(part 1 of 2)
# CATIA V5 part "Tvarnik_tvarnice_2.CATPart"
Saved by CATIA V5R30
Part number: Tvarnik_tvarnice_1
Bounding box of the stored display mesh (mm): x -44.4 to 47.6, y -90 to 90, z -90 to 90
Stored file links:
  E:\Bakalarka\Model\Forma_v7\Tvarnik_tvarnice_2.CATPart
  E:\Bakalarka\Model\Sestava_formy_1\Vicko.CATPart
  E:\Bakalarka\Model\Sestava_formy\Tvarnik_tvarnice.CATPart
  E:\Bakalarka\Model\Forma_v7\Sestava_tvarniku_tvarnice.CATProduct
  E:\Bakalarka\Model\Sestava_formy_1\Forma_Sestava_tvarniku_tvarnice.CATPart
  E:\Bakalarka\Model\Chyba catie 2\Forma_Sestava_tvarniku_tvarnice.CATPart
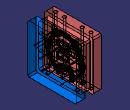
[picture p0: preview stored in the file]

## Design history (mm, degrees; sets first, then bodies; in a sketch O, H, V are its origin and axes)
Body1 (main body)
  Solid1: solid without history
  Body2 "Result of __DrillHole"
    Solid2: linked copy from another document
  Assemble1 "DrillHoleEjector_E1710_7.1": tool Body2
  Body3 "Result of __DrillHole"
    Solid3: linked copy from another document
  Assemble2 "DrillHoleEjector_E1710_8.1": tool Body3
  Body4 "Result of __DrillHole"
    Solid4: linked copy from another document
  Assemble3 "DrillHoleEjector_E1710_9.1": tool Body4
  Body5 "Result of __DrillHole"
    Solid5: linked copy from another document
  Assemble4 "DrillHoleEjector_E1710_10.1": tool Body5
  Body6 "Result of __DrillHole"
    Solid6: linked copy from another document
  Assemble5 "DrillHoleEjector_E1710_11.1": tool Body6
  Body7 "Result of __DrillHole"
    Solid7: linked copy from another document
  Assemble6 "DrillHoleEjector_E1710_17.1": tool Body7
  Body8 "Result of __DrillHole"
    Solid8: linked copy from another document
  Assemble7 "DrillHoleEjector_E1710_18.1": tool Body8
  Body9 "Result of __DrillHole"
    Solid9: linked copy from another document
  Assemble8 "DrillHoleEjector_E1710_19.1": tool Body9
  Body10 "Result of __DrillHole"
    Solid10: linked copy from another document
  Assemble9 "DrillHoleEjector_E1710_20.1": tool Body10
  Body11 "Result of __DrillHole"
    Solid11: linked copy from another document
  Assemble10 "DrillHoleEjector_E1710_21.1": tool Body11
  Body12 "Result of __DrillHole"
    Solid12: linked copy from another document
  Assemble11 "DrillHoleEjector_E1710_31.1": tool Body12
  Body13 "Result of __DrillHole"
    Solid13: linked copy from another document
  Assemble12 "DrillHoleEjector_E1710_32.1": tool Body13
  Body14 "Result of __DrillHole"
    Solid14: linked copy from another document
  Assemble13 "DrillHoleEjector_E1710_33.1": tool Body14
  Body15 "Result of __DrillHole"
    Solid15: linked copy from another document
  Assemble14 "DrillHoleEjector_E1710_34.1": tool Body15
  Body16 "Result of __DrillHole"
    Solid16: linked copy from another document
  Assemble15 "DrillHoleEjector_E1710_35.1": tool Body16
  Body17 "Result of __DrillHole"
    Solid17: linked copy from another document
  Assemble16 "DrillHoleEjector_E1710_36.1": tool Body17
  Body18 "Result of __DrillHole"
    Solid18: linked copy from another document
  Assemble17 "DrillHoleEjector_E1710_37.1": tool Body18
  Body19 "Result of __DrillHole"
    Solid19: linked copy from another document
  Assemble18 "DrillHoleEjector_E1710_1.2": tool Body19
  Body20 "Result of __DrillHole"
    Solid20: linked copy from another document
  Assemble19 "DrillHoleEjector_E1710_2.2": tool Body20
  Body21 "Result of __DrillHole"
    Solid21: linked copy from another document
  Assemble20 "DrillHoleEjector_E1710_3.2": tool Body21
  Body22 "Result of __DrillHole"
    Solid22: linked copy from another document
  Assemble21 "DrillHoleEjector_E1710_4.2": tool Body22
Body23 "Tvarnik"
  Sketch1 on face of Solid23, origin (1.6, 0, 0), H (0, 1, 0), V (0, 0, 1)
    line L1 (80, 80) -> (80, -80)
    line L2 (80, -80) -> (-80, -80)
    line L3 (-80, -80) -> (-80, 80)
    line L4 (-80, 80) -> (80, 80)
    length L4 = 160
    length L1 = 160
    vertical: L1 V, L3 V
    horizontal: L2 H, L4 H
    equidistance: L1 L3 O, L2 L4 O
  Pad1: profile Sketch1, direction (-1, 0, 0), length 16
  Body24 "Vicko"
    Solid23: linked copy from another document
  Remove1: tool Body24
  Sketch2 on start face of Pad1, origin (1.6, 0, 0), H (0, 1, 0), V (0, 0, 1)
    projected arc E1 centre (0, 0) radius 71.425 from (33.2826, 63.1965) to (-30.4134, 64.6263) ccw from edge [face of Solid23 | face of Solid23]
    projected arc E2 centre (-31.265, 66.4359) radius 2 from (-30.8799, 64.4733) to (-30.4134, 64.6263) ccw from edge [face of Solid23 | face of Solid23]
    projected arc E3 centre (-31.265, 66.4359) radius 2 from (-32.3394, 64.749) to (-30.8799, 64.4733) ccw from edge [face of Solid23 | face of Solid23]
    projected arc E4 centre (-35.5625, 59.6882) radius 6 from (-32.3394, 64.749) to (-41.5474, 59.2628) ccw from edge [face of Solid23 | face of Solid23]
    projected arc E5 centre (-43.5423, 59.121) radius 2 from (-42.3563, 57.5107) to (-41.5474, 59.2628) ccw from edge [face of Solid23 | face of Solid23]
    projected arc E6 centre (0, 0) radius 71.425 from (-42.3563, 57.5107) to (-68.5299, 20.1291) ccw from edge [face of Solid23 | face of Solid23]
    projected arc E7 centre (-70.4489, 20.6927) radius 2 from (-69.8997, 18.7696) to (-68.5299, 20.1291) ccw from edge [face of Solid23 | face of Solid23]
    projected arc E8 centre (-68.2522, 13.0002) radius 6 from (-69.8997, 18.7696) to (-71.9052, 8.2404) ccw from edge [face of Solid23 | face of Solid23]
    projected arc E9 centre (-73.1229, 6.6538) radius 2 from (-71.1311, 6.4726) to (-71.9052, 8.2404) ccw from edge [face of Solid23 | face of Solid23]
    projected arc E10 centre (0, 0) radius 71.425 from (-71.1311, 6.4726) to (-64.1739, -31.3568) ccw from edge [face of Solid23 | face of Solid23]
    projected arc E11 centre (0, 0) radius 71.425 from (-64.1739, -31.3568) to (-44.634, -55.7614) ccw from edge [face of Solid23 | face of Solid23]
    projected arc E12 centre (-44.9464, -56.1518) radius 0.5 from (-44.5334, -55.87) to (-44.634, -55.7614) ccw from edge [face of Solid23 | face of Solid23]
    projected line E13 (-44.5334, -55.87) -> (-43.5459, -57.3175) from edge [face of Solid23 | face of Solid23]
    projected arc E14 centre (-43.1328, -57.0357) radius 0.5 from (-43.5459, -57.3175) to (-42.9183, -57.4874) ccw from edge [face of Solid23 | face of Solid23]
    projected line E15 (-42.9183, -57.4874) -> (-42.6019, -57.337) from edge [face of Solid23 | face of Solid23]
    projected arc E16 centre (-42.6448, -57.2467) radius 0.1 from (-42.6019, -57.337) to (-42.5892, -57.3299) ccw from edge [face of Solid23 | face of Solid23]
    projected arc E17 centre (-38.7, -63.15) radius 7 from (-37.0577, -56.3454) to (-42.5892, -57.3299) ccw from edge [face of Solid23 | face of Solid23]
    projected arc E19 centre (-39.7026, -63.67) radius 8 from (-33.5229, -68.7505) to (-31.75, -64.54) ccw from edge [face of Solid23 | face of Solid23]
    projected arc E20 centre (-33.4456, -68.814) radius 0.1 from (-33.5229, -68.7505) to (-33.494, -68.9015) ccw from edge [face of Solid23 | face of Solid23]
    projected line E21 (-33.494, -68.9015) -> (-28.2581, -71.7985) from edge [face of Solid23 | face of Solid23]
    projected line E22 (-25.7474, -73.1876) -> (-28.2581, -71.7985) from edge [face of Solid23 | face of Solid23]
    projected arc E23 centre (-25.7, -67.2) radius 6 from (-25.7, -73.2) to (-19.7, -67.2) ccw from edge [face of Solid23 | face of Solid23]
    projected line E24 (-19.7, -52.2166) -> (-19.7, -67.2) from edge [face of Solid23 | face of Solid23]
    projected arc E25 centre (-12.6167, -52.2166) radius 7.0833 from (-14.8563, -45.4967) to (-19.7, -52.2166) ccw from edge [face of Solid23 | face of Solid23]
    projected arc E26 centre (-12.6167, -52.2166) radius 7.0833 from (-13.7, -45.2166) to (-14.8563, -45.4967) ccw from edge [face of Solid23 | face of Solid23]
    projected arc E27 centre (-1.5593, -117.2) radius 73 from (8.5876, -44.9086) to (-13.7, -45.2166) ccw from edge [face of Solid23 | face of Solid23]
    projected arc E28 centre (-1.5593, -117.2) radius 73 from (12.028, -45.4756) to (8.5876, -44.9086) ccw from edge [face of Solid23 | face of Solid23]
    projected arc E29 centre (10.55, -54.5084) radius 9.15 from (14.5407, -46.2746) to (12.2, -45.5084) ccw from edge [face of Solid23 | face of Solid23]
    projected arc E30 centre (-1.5593, -117.2) radius 73 from (12.2, -45.5084) to (12.028, -45.4756) ccw from edge [face of Solid23 | face of Solid23]
    projected arc E31 centre (10.55, -54.5084) radius 9.15 from (19.7, -54.5084) to (14.5407, -46.2746) ccw from edge [face of Solid23 | face of Solid23]
    projected line E32 (19.7, -54.5084) -> (19.7, -65.95) from edge [face of Solid23 | face of Solid23]
    projected arc E33 centre (26.95, -65.95) radius 7.25 from (19.7, -65.95) to (26.95, -73.2) ccw from edge [face of Solid23 | face of Solid23]
    projected line E34 (26.95, -73.2) -> (27.1807, -73.2) from edge [face of Solid23 | face of Solid23]
    projected line E35 (27.2179, -73.1928) -> (29.0487, -72.4522) from edge [face of Solid23 | face of Solid23]
    projected line E36 (27.2179, -73.1928) -> (27.1999, -73.1995) from edge [face of Solid23 | face of Solid23]
    projected line E37 (27.1999, -73.1995) -> (27.1807, -73.2) from edge [face of Solid23 | face of Solid23]
    projected arc E38 centre (27.2, -65.7) radius 7 from (29.0596, -72.4485) to (34.2, -65.7) ccw from edge [face of Solid23 | face of Solid23]
    projected line E39 (29.054, -72.45) -> (29.0596, -72.4485) from edge [face of Solid23 | face of Solid23]
    projected line E40 (29.0487, -72.4522) -> (29.054, -72.45) from edge [face of Solid23 | face of Solid23]
    projected arc E41 centre (39.6, -65.7) radius 5.4 from (34.6823, -63.4692) to (34.2, -65.7) ccw from edge [face of Solid23 | face of Solid23]
    projected line E42 (34.6907, -63.4503) -> (34.6823, -63.4692) from edge [face of Solid23 | face of Solid23]
    projected arc E43 centre (34.5768, -63.4037) radius 0.123 from (34.6907, -63.4503) to (34.6998, -63.4087) ccw from edge [face of Solid23 | face of Solid23]
    projected line E44 (34.7, -63.3874) -> (34.6998, -63.4087) from edge [face of Solid23 | face of Solid23]
    projected line E45 (34.7, -63.3874) -> (34.7, -62.4295) from edge [face of Solid23 | face of Solid23]
    projected arc E46 centre (0, 0) radius 71.425 from (34.7, -62.4295) to (69.8826, -14.7632) ccw from edge [face of Solid23 | face of Solid23]
    projected arc E47 centre (70.861, -14.9699) radius 1 from (70.1987, -14.2207) to (69.8826, -14.7632) ccw from edge [face of Solid23 | face of Solid23]
    projected line E48 (70.1987, -14.2207) -> (71.6567, -12.9317) from edge [face of Solid23 | face of Solid23]
    projected line E49 (71.6567, -12.9317) -> (72.0071, -12.6219) from edge [face of Solid23 | face of Solid23]
    projected line E50 (72.1405, -12.504) -> (72.0071, -12.6219) from edge [face of Solid23 | face of Solid23]
    projected arc E51 centre (72.4717, -12.8786) radius 0.5 from (72.2645, -12.4235) to (72.1405, -12.504) ccw from edge [face of Solid23 | face of Solid23]
    projected arc E52 centre (69.7785, -6.9628) radius 6 from (72.2645, -12.4235) to (75.4588, -5.0305) ccw from edge [face of Solid23 | face of Solid23]
    projected line E53 (70.9819, 8.13) -> (75.4588, -5.0305) from edge [face of Solid23 | face of Solid23]
    projected arc E54 centre (69.5316, 12.3887) radius 4.4 from (65.7164, 14.5806) to (70.8571, 8.1931) ccw from edge [face of Solid23 | face of Solid23]
    projected line E55 (65.7164, 14.5806) -> (68.6344, 19.6597) from edge [face of Solid23 | face of Solid23]
    projected arc E56 centre (68.5476, 19.7096) radius 0.1001 from (68.6357, 19.662) to (68.6445, 19.7346) ccw from edge [face of Solid23 | face of Solid23]
    projected arc E57 centre (0, 0) radius 71.425 from (68.6438, 19.7372) to (44.8942, 55.5522) ccw from edge [face of Solid23 | face of Solid23]
    projected arc E58 centre (46.1513, 57.1077) radius 2 from (44.1679, 56.8506) to (44.8942, 55.5522) ccw from edge [face of Solid23 | face of Solid23]
    projected arc E59 centre (46.1513, 57.1077) radius 2 from (44.1647, 57.3389) to (44.1679, 56.8506) ccw from edge [face of Solid23 | face of Solid23]
    projected arc E60 centre (38.2049, 58.0324) radius 6 from (44.1647, 57.3389) to (35.2121, 63.2327) ccw from edge [face of Solid23 | face of Solid23]
    projected arc E61 centre (34.2145, 64.9661) radius 2 from (34.4133, 62.976) to (35.2121, 63.2327) ccw from edge [face of Solid23 | face of Solid23]
    projected arc E62 centre (34.2145, 64.9661) radius 2 from (33.2826, 63.1965) to (34.4133, 62.976) ccw from edge [face of Solid23 | face of Solid23]
    line L1 (68.6445, 19.7346) -> (68.6437, 19.7374)
    line L2 (-25.7, -73.2) -> (-25.7474, -73.1876)
    arc A1 centre (70.8987, 8.1188) radius 0.0834 from (70.9741, 8.1546) to (70.8713, 8.1976) ccw
    line L3 (70.8571, 8.1931) -> (70.8673, 8.1964)
    line L4 (70.9819, 8.13) -> (70.9741, 8.1546)
    point P129 (70.8713, 8.1976)
    line L5 (70.8673, 8.1964) -> (70.8713, 8.1976)
    point P130 (70.8713, 8.1976)
    line L6 (68.6344, 19.6597) -> (68.6357, 19.662)
    projected line E63 (-80, -80) -> (80, -80) from edge [face of Pad1 from Sketch1.L2 | start face of Pad1]
    projected line E64 (80, -80) -> (80, 80) from edge [face of Pad1 from Sketch1.L1 | start face of Pad1]
    projected line E65 (80, 80) -> (-80, 80) from edge [face of Pad1 from Sketch1.L4 | start face of Pad1]
    projected line E66 (-80, 80) -> (-80, -80) from edge [face of Pad1 from Sketch1.L3 | start face of Pad1]
    radius A1 = 0.0834
    distance P130 P129 = 0
    tangency: L1 E57, A1 E54, L3 E54
    perpendicularity: L4 L3
    coincidence: L3 P129, P130 E54
  Pocket1: profile Sketch2, direction (-1, 0, 0), length 16
  Sketch3 on end face of Pad1, origin (-14.4, 0, 0), H (0, -1, 0), V (0, 0, 1)
    line L1 (85.4438, 86.0089) -> (85.4438, -86.0089)
    line L2 (85.4438, -86.0089) -> (-85.4438, -86.0089)
    line L3 (-85.4438, -86.0089) -> (-85.4438, 86.0089)
    line L4 (-85.4438, 86.0089) -> (85.4438, 86.0089)
    projected circle E1 centre (35.5625, 59.6882) radius 5.1 from edge [face of Solid23 | start face of Pad1]
    projected circle E2 centre (-38.2049, 58.0324) radius 5.1 from edge [face of Solid23 | start face of Pad1]
    projected circle E3 centre (-70.2785, -7.2128) radius 5.1 from start face of Pad1
    projected circle E4 centre (-26.45, -66.45) radius 5.1 from edge [face of Solid23 | start face of Pad1]
    projected circle E5 centre (26.2, -66.08) radius 5.1 from edge [face of Solid23 | start face of Pad1]
    projected circle E6 centre (68.2522, 13.0002) radius 5.1 from start face of Pad1
    length L4 = 170.8876
    length L1 = 172.0179
    vertical: L1 V, L3 V
    horizontal: L2 H, L4 H
    equidistance: L1 L3 O, L2 L4 O
  Pocket2: profile Sketch3, direction (1, 0, 0), through (limit type 6)
  Sketch4 on end face of Pad1, origin (-14.4, 0, 0), H (0, -1, 0), V (0, 0, 1)
    projected circle E1 centre (68.2522, 13.0002) radius 5.1 from end face of Pad1
    projected circle E2 centre (35.5625, 59.6882) radius 5.1 from end face of Pad1
    projected circle E3 centre (-38.2049, 58.0324) radius 5.1 from end face of Pad1
    projected circle E4 centre (-70.2785, -7.2128) radius 5.1 from end face of Pad1
    projected circle E5 centre (-26.45, -66.45) radius 5.1 from end face of Pad1
    projected circle E6 centre (26.2, -66.08) radius 5.1 from end face of Pad1
  Pocket3: profile Sketch4, direction (1, 0, 0), length 12.7
  Sketch5 on start face of Pad1, origin (1.6, 0, 0), H (0, 1, 0), V (0, 0, 1)
    point P1 (0, 0)
    line L1 (80, 80) -> (80, -80)
    line L2 (80, -80) -> (-80, -80)
    line L3 (-80, -80) -> (-80, 80)
    line L4 (-80, 80) -> (80, 80)
    length L4 = 160
    length L1 = 160
    distance V L1 = 80
    coincidence: P1 H
    vertical: L1 V, L3 V
    horizontal: L2 H, L4 H
    equidistance: L1 L3 P1, L2 L4 P1
  Pad2: profile Sketch5, direction (1, 0, 0), length 16
  Sketch6 on start face of Pad2, origin (1.6, 0, 0), H (0, -1, 0), V (0, 0, 1)
  Pocket4: profile Sketch6, direction (1, 0, 0), length 1
  Fillet1: radius 0.5, on end face of Pocket4
  Fillet2: radius 0.5, on edge [start face of Pad2 | face of Pocket4] (x12)
  Fillet3: radius 0.1, on edge [face of Solid23 | face of Solid23] (x3)
  Fillet4: radius 0.1, on edge [face of Solid23 | face of Solid23] (x3)
  Fillet5: radius 0.1, on edge [face of Solid23 | face of Solid23] (x2)
  Fillet6: radius 0.05, on edge [face of Solid23 | face of Solid23]
  Fillet7: radius 0.1, on edge [face of Solid23 | start face of Pad2] (x2); edge [start face of Pad2 | face of Solid23] (x3)
  Fillet8: radius 0.1, on edge [face of Solid23 | face of Solid23]
  Sketch7 on end face of Pad2, origin (17.6, 0, 0), H (0, 1, 0), V (0, 0, 1)
    line L1 (90, 90) -> (90, -90)
    line L2 (90, -90) -> (-90, -90)
    line L3 (-90, -90) -> (-90, 90)
    line L4 (-90, 90) -> (90, 90)
    length L4 = 180
    length L1 = 180
    vertical: L1 V, L3 V
    horizontal: L2 H, L4 H
    equidistance: L1 L3 O, L2 L4 O
  Pad3: profile Sketch7, direction (1, 0, 0), length 30
  Sketch8 on end face of Pocket3, origin (-1.7, 0, 0), H (0, -1, 0), V (0, 0, 1)
    point P1 (-69.8618, -2.2572)
    line L1 (-67.3618, -1.8448) -> (-67.3618, -2.6696)
    line L2 (-67.3618, -2.6696) -> (-72.3618, -2.6696)
    line L3 (-72.3618, -2.6696) -> (-72.3618, -1.8448)
    line L4 (-72.3618, -1.8448) -> (-67.3618, -1.8448)
    length L4 = 5
    vertical: L1 V, L3 V
    horizontal: L2 H, L4 H
    equidistance: L1 L3 P1, L2 L4 P1
  Pocket5: profile Sketch8, direction (1, 0, 0), length 1
  Sketch9 on start face of Pad2, origin (1.6, 0, 0), H (0, -1, 0), V (0, 0, 1)
    point P1 (-45.5, 54.5)
    point P2 (-64.5, 22.5)
    point P3 (-69.5, 0)
    point P4 (-35.5, -4)
    point P5 (-18, 20)
    point P6 (10, 25)
    point P7 (5, 44.5)
    point P8 (23.5, 54.5)
    point P9 (43, 53.5)
    point P10 (66, 21.5)
    point P11 (60, 15)
    point P12 (45, -10)
    point P13 (35.5, -45)
    point P14 (-30, -57.5)
    point P15 (-35, -53)
    point P16 (-35.5, -33)
    point P17 (-32, 61)
    construction circle A1 centre (35.5, -45) radius 4.5
    construction circle A2 centre (45, -10) radius 4.5
    construction circle A3 centre (66, 21.5) radius 2
    construction circle A4 centre (60, 15) radius 1.15
    construction circle A5 centre (43, 53.5) radius 1.15
    construction circle A6 centre (23.5, 54.5) radius 2
    construction circle A7 centre (5, 44.5) radius 4.5
    construction circle A8 centre (-35.5, -4) radius 2
    construction circle A9 centre (-69.5, 0) radius 2
    construction circle A10 centre (-64.5, 22.5) radius 2
    construction circle A11 centre (-45.5, 54.5) radius 2
    construction circle A12 centre (-18, 20) radius 4.5
    construction circle A13 centre (10, 25) radius 2
    construction circle A14 centre (-35.5, -33) radius 2
    construction circle A15 centre (-35, -53) radius 1.15
    construction circle A16 centre (-30, -57.5) radius 2
    construction line L1 (-85, 90) -> (85, 90)
    construction line L2 (-90, -85) -> (-90, 85)
    reference projected line E1 (-90, 90) -> (90, 90) from edge [start face of Pad3 | face of Pad3 from Sketch7.L4]
    reference projected line E2 (-90, -90) -> (-90, 90) from edge [start face of Pad3 | face of Pad3 from Sketch7.L1]
    reference projected line E3 (90, -90) -> (-90, -90) from edge [start face of Pad3 | face of Pad3 from Sketch7.L2]
    reference projected line E4 (90, 90) -> (90, -90) from edge [start face of Pad3 | face of Pad3 from Sketch7.L3]
    reference projected line E5 (80, -80) -> (-80, -80) from edge [start face of Pad2 | face of Pad2 from Sketch5.L2]
    reference projected line E6 (-80, 80) -> (80, 80) from edge [start face of Pad2 | face of Pad2 from Sketch5.L4]
    reference projected line E7 (80, 80) -> (80, -80) from edge [start face of Pad2 | face of Pad2 from Sketch5.L3]
    distance P17 L1 = 29
    distance P17 L2 = 58
    distance P17 E1 = 29
    distance P17 E2 = 58
    distance P1 E2 = 44.5
    distance P1 E1 = 35.5
    distance P2 E2 = 25.5
    distance P2 E1 = 67.5
    distance P3 E2 = 20.5
    distance P16 E3 = 57
    distance P15 E3 = 37
    distance P14 E3 = 32.5
    distance P14 E2 = 60
    distance P15 E2 = 55
    distance P16 E2 = 54.5
    distance P4 E2 = 54.5
    distance P4 E3 = 86
    distance P13 E3 = 45
    distance P13 E4 = 54.5
    distance P12 E4 = 45
    distance P12 E5 = 70
    distance P11 E4 = 30
    distance P11 E6 = 65
    distance P10 E7 = 14
    distance P10 E6 = 58.5
    distance P9 E6 = 26.5
    distance P9 E7 = 37
    distance P7 E6 = 35.5
    distance P7 E7 = 75
    distance P8 E6 = 25.5
    distance P8 E7 = 56.5
    distance E6 P5 = 60
    distance P5 E2 = 72
    distance P6 E2 = 100
    distance P6 E1 = 65
    concentricity: P1 A11, P2 A10, P3 A9, P4 A8, P5 A12, P6 A13, P7 A7, P8 A6, P9 A5, P10 A3, P11 A4, P12 A2, P13 A1, P14 A16, P15 A15, P16 A14
  DatumSurface1
  DatumSurface2
  DatumCurve1
  DatumSurface3
  DatumCurve2
  DatumSurface4 to DatumSurface8
  DatumCurve3 to DatumCurve7
  DatumSurface9
  DatumSurface10
  Sketch10 on face of Solid23, origin (-0.7, 0, 0), H (0, -1, 0), V (0, 0, 1)
    projected circle E1 centre (35.5, -45) radius 3.5 from face of DatumSurface1
    projected circle E2 centre (45, -10) radius 3.5 from face of DatumSurface2
    projected circle E3 centre (60, 15) radius 1.25 from edge of DatumCurve1
    projected circle E4 centre (66, 21.5) radius 2 from face of DatumSurface3
    projected circle E5 centre (43, 53.5) radius 1.25 from edge of DatumCurve2
    projected circle E6 centre (23.5, 54.5) radius 2 from face of DatumSurface4
    projected circle E7 centre (5, 44.5) radius 3.5 from face of DatumSurface5
    projected circle E8 centre (10, 25) radius 3.5 from face of DatumSurface6
    projected circle E9 centre (-18, 20) radius 3.5 from face of DatumSurface7
    projected circle E10 centre (-32, 61) radius 1.25 from face of DatumSurface8
    projected circle E11 centre (-45.5, 54.5) radius 1.25 from edge of DatumCurve3
    projected circle E12 centre (-64.5, 22.5) radius 2 from edge of DatumCurve4
    projected circle E13 centre (-69.5, 0) radius 2 from edge of DatumCurve5
    projected circle E14 centre (-30, -57.5) radius 1.25 from edge of DatumCurve7
    projected circle E15 centre (-35.5, -33) radius 3.5 from face of DatumSurface9
    projected circle E16 centre (-35.5, -4) radius 3.5 from face of DatumSurface10
  Pocket6: profile Sketch10, direction (1, 0, 0), through (limit type 6)
  Sketch11 on face of Solid23, origin (-2.9, 0, 0), H (0, -1, 0), V (0, 0, 1)
    projected circle E1 centre (10, 25) radius 3.5 from edge [end face of Pad3 | face of Pocket6 from Sketch10.E8]
  Pocket7: profile Sketch11, direction (1, 0, 0), through (limit type 6)
  DatumCurve8 to DatumCurve21
  DatumSurface11
  Sketch12 on start face of Pad2, origin (1.6, 0, 0), H (0, -1, 0), V (0, 0, 1)
    projected arc E1 centre (1.1787, -116.2024) radius 72.9279 from (-2.5137, -43.3681) to (-11.5873, -44.4006) ccw from edge of DatumCurve13
    point P4 (-12, -49.5001)
    projected line E2 (10.5, -50.0001) -> (-11.5, -50.0001) from edge of DatumCurve19
    point P5 (10.5, -50.0001)
    point P6 (-11.5, -50.0001)
    projected line E3 (11.5, -50.0001) -> (10.5, -50.0001) from edge of DatumCurve20
    projected line E4 (11, -50.0001) -> (10.5, -50.0001) from edge of DatumCurve20
    point P8 (10.5, -50.0001)
    projected line E5 (-11.5, -50.0001) -> (-12.5, -50.0001) from edge of DatumCurve21
    projected line E6 (-11.5, -50.0001) -> (-12, -50.0001) from edge of DatumCurve21
    point P9 (-11.5, -50.0001)
    line L1 (-12, -49.5001) -> (-12, -50.0001)
    point P11 (-12, -50.0001)
    line L2 (11, -49.5001) -> (11, -50.0001)
    point P12 (11, -50.0001)
    offset arc E7 centre (1.1786, -116.2024) radius 72.4278 from (-2.4884, -43.8674) to (-11.4998, -44.8928) ccw from edge of DatumCurve13
    point P13 (-2.4884, -43.8674)
    offset arc E8 centre (1.1746, -116.163) radius 72.3883 from (10.4999, -44.3778) to (-2.4622, -43.8661) ccw from edge of DatumCurve11
    point P17 (-2.4884, -43.8674)
    line L3 (10.4999, -44.3778) -> (11, -44.4428)
    line L4 (-11.4998, -44.8928) -> (-12, -44.9824)
    line L5 (-12, -44.9824) -> (-12, -49.5001)
    point P20 (-12, -49.5001)
    line L6 (-2.4884, -43.8674) -> (-2.4622, -43.8661)
    line L7 (11, -44.4428) -> (11, -49.5001)
    distance P20 P4 = 0
    midpoint: P11 E5, P12 E3
    vertical: L1 V, L2 V, L5 V, L7 V
    coincidence: P5 P8, P6 P9, E8 P17, P17 P13
    tangency: E8 E7, L3 E8, L4 E8, L6 E8
  Pad4: profile Sketch12, direction (-1, 0, 0), up to face of DatumSurface11
  Fillet9: radius 0.5, on edge [start face of Pad2 | face of Pad4 from Sketch12.E2]; edge [end face of Pad4 | face of Pad4 from Sketch12.E2]
  DatumSurface12 to DatumSurface15
  Sketch13 on end face of Pad3, origin (47.6, 0, 0), H (0, 1, 0), V (0, 0, 1)
    projected circle E1 centre (-2, -31) radius 3 from face of DatumSurface12
    projected circle E2 centre (-10, -12) radius 3 from face of DatumSurface13
    projected circle E3 centre (178, -31) radius 3 from face of DatumSurface14
    projected circle E4 centre (170, -12) radius 3 from face of DatumSurface15
  DatumSurface16
  DatumSurface17
  Sketch14 on face of Pad3, origin (47.6, 0, 0), H (0, 1, 0), V (0, 0, 1)
    projected circle E1 centre (-2, -31) radius 3 from face of DatumSurface16
    projected circle E2 centre (-10, -12) radius 3 from face of DatumSurface17
  Pocket8: profile Sketch14, direction (-1, 0, 0), length 100
  Pad5: profile Sketch13, direction (-1, 0, 0), length 100
  Sketch15 on end face of Pad5, origin (-52.4, 0, 0), H (0, -1, 0), V (0, 0, 1)
    projected circle E1 centre (-170, -12) radius 3 from end face of Pad5
    projected circle E2 centre (-178, -31) radius 3 from end face of Pad5
  Pocket9: profile Sketch15, direction (1, 0, 0), length 100
  Sketch16 on end face of Pad5, origin (-52.4, 0, 0), H (0, -1, 0), V (0, 0, 1)
    projected circle E1 centre (10, -12) radius 3 from edge [end face of Pad5 | face of Pad5 from Sketch13.E2]
    projected circle E2 centre (2, -31) radius 3 from end face of Pad5
  Pocket10: profile Sketch16, direction (1, 0, 0), length 100
  Chamfer1: length 5, angle 45, on edge [face of Pad2 from Sketch5.L2 | face of Pad2 from Sketch5.L3]; edge [face of Pad3 from Sketch7.L2 | face of Pad3 from Sketch7.L3]; edge [face of Pad2 from Sketch5.L3 | face of Pad2 from Sketch5.L4]; edge [face of Pad3 from Sketch7.L3 | face of Pad3 from Sketch7.L4]; edge [face of Pad3 from Sketch7.L4 | face of Pad3 from Sketch7.L1]; edge [face of Pad2 from Sketch5.L4 | face of Pad2 from Sketch5.L1]; edge [face of Pad3 from Sketch7.L1 | face of Pad3 from Sketch7.L2]; edge [face of Pad2 from Sketch5.L1 | face of Pad2 from Sketch5.L2]
  Sketch17 on face of Pad2 from Sketch5.L2, origin (0, 0, -80), H (1, 0, 0), V (0, -1, 0)
    circle A1 centre (9.6, -55) radius 5
    point P1 (9.6, -55)
    point P2 (9.6, 53.5)
    reference projected line E1 (1.6, 80) -> (1.6, -80) from edge [start face of Pad2 | face of Pad2 from Sketch5.L2]
    reference projected line E2 (1.6, -75) -> (17.6, -75) from edge [face of Chamfer1 | face of Pad2 from Sketch5.L2]
    reference projected line E3 (1.6, 75) -> (17.6, 75) from edge [face of Pad2 from Sketch5.L2 | face of Chamfer1]
    radius A1 = 5
    distance P1 E1 = 8
    distance P2 E1 = 8
    distance P1 E2 = 20
    distance E3 P2 = 21.5
  Pocket11: profile Sketch17, direction (0, 0, 1), through (limit type 3)
  DatumPoint1 to DatumPoint4
  Sketch18 on face of Pad2 from Sketch5.L1, origin (0, 80, 0), H (-1, 0, 0), V (0, 0, 1)
    projected point E1 (-9.6, -22) from vertex of DatumPoint1
    projected point E2 (-9.6, -45) from vertex of DatumPoint2
    projected point E3 (-9.6, 8) from vertex of DatumPoint3
    projected point E4 (-9.6, 34.5) from vertex of DatumPoint4
  Sketch19 on face of Pad2 from Sketch5.L1, origin (9.6, 80, -45), H (1, 0, 0), V (0, 0, -1)
    point P1 (0, 0)
    reference projected point E1 (0, 0) from vertex of Sketch18.E2
    coincidence: E1 P1
  Hole1: placed by Sketch19, at (9.6, 80, -45) direction (0, -1, 0), diameter 10, depth 95, V-bottom angle 120
  Sketch20 on face of Pad2 from Sketch5.L1, origin (9.6, 80, 34.5), H (1, 0, 0), V (0, 0, -1)
    point P1 (0, 0)
    reference projected point E1 (0, 0) from vertex of Sketch18.E4
    coincidence: E1 P1
  Hole2: placed by Sketch20, at (9.6, 80, 34.5) direction (0, -1, 0), diameter 10, depth 300, V-bottom angle 120
  Sketch21 on face of Pad2 from Sketch5.L1, origin (9.6, 80, -22), H (1, 0, 0), V (0, 0, -1)
    point P1 (0, 0)
    reference projected point E1 (0, 0) from vertex of Sketch18.E1
    coincidence: E1 P1
  Hole3: placed by Sketch21, at (9.6, 80, -22) direction (0, -1, 0), diameter 10, depth 300, V-bottom angle 120
  Sketch22 on face of Pad2 from Sketch5.L3, origin (0, -80, 0), H (1, 0, 0), V (0, 0, 1)
    projected point E1 (9.6, -22) from vertex of Sketch18.E1
    projected point E2 (9.6, 8) from vertex of Sketch18.E3
    projected point E3 (9.6, 34.5) from vertex of Sketch18.E4
  Sketch23 on face of Pad2 from Sketch5.L3, origin (9.6, -80, 34.5), H (1, 0, 0), V (0, 0, 1)
    point P1 (0, 0)
    reference projected point E1 (0, 0) from vertex of Sketch22.E3
    coincidence: E1 P1
  Hole4: placed by Sketch23, at (9.6, -80, 34.5) direction (0, 1, 0), diameter 10.376, depth 43, V-bottom angle 120, threaded "M12x1.5", thread diameter 12, thread depth 41, pitch 1.5
  Sketch24 on face of Pad2 from Sketch5.L3, origin (9.6, -80, -22), H (1, 0, 0), V (0, 0, 1)
    point P1 (0, 0)
    reference projected point E1 (0, 0) from vertex of Sketch22.E1
    coincidence: E1 P1
  Hole5: placed by Sketch24, at (9.6, -80, -22) direction (0, 1, 0), diameter 10.376, depth 23, V-bottom angle 120, threaded "M12x1.5", thread diameter 12, thread depth 22, pitch 1.5
  Sketch25 on face of Pad2 from Sketch5.L1, origin (9.6, 80, -22), H (1, 0, 0), V (0, 0, -1)
    point P1 (0, 0)
    reference projected point E1 (0, 0) from vertex of Sketch18.E1
    coincidence: E1 P1
  Hole6: placed by Sketch25, at (9.6, 80, -22) direction (0, -1, 0), diameter 10.376, depth 24, V-bottom angle 120, threaded "M12x1.5", thread diameter 12, thread depth 22, pitch 1.5
  Sketch26 on face of Pad2 from Sketch5.L1, origin (9.6, 80, 34.5), H (1, 0, 0), V (0, 0, -1)
    point P1 (0, 0)
    reference projected point E1 (0, 0) from vertex of Sketch18.E4
    coincidence: E1 P1
  Hole7: placed by Sketch26, at (9.6, 80, 34.5) direction (0, -1, 0), diameter 10.376, depth 22, V-bottom angle 120, threaded "M12x1.5", thread diameter 12, thread depth 20, pitch 1.5
  Sketch27 on face of Pad2 from Sketch5.L1, origin (9.6, 80, -45), H (1, 0, 0), V (0, 0, -1)
    point P1 (0, 0)
    reference projected point E1 (0, 0) from vertex of Sketch18.E2
    coincidence: E1 P1
  Hole8: placed by Sketch27, at (9.6, 80, -45) direction (0, -1, 0), diameter 10.376, depth 13, V-bottom angle 120, threaded "M12x1.5", thread diameter 12, thread depth 10, pitch 1.5
  Sketch28 on face of Pad2 from Sketch5.L4, origin (0, 0, 80), H (1, 0, 0), V (0, 1, 0)
    point P1 (9.6, -53.5)
    point P2 (9.6, 55)
    reference projected line E1 (17.6, 90) -> (17.6, -90) from edge [start face of Pad3 | face of Pad3 from Sketch7.L4]
    reference projected line E2 (1.6, 75) -> (17.6, 75) from edge [face of Pad2 from Sketch5.L4 | face of Chamfer1]
    reference projected line E3 (1.6, -75) -> (17.6, -75) from edge [face of Chamfer1 | face of Pad2 from Sketch5.L4]
    distance P2 E1 = 8
    distance P2 E2 = 20
    distance P1 E3 = 21.5
    distance P1 E1 = 8
  Sketch29 on face of Pad2 from Sketch5.L4, origin (9.6, 55, 80), H (1, 0, 0), V (0, 1, 0)
    point P1 (0, 0)
    reference projected point E1 (0, 0) from Sketch28.P2
    coincidence: E1 P1
  Hole9: placed by Sketch29, at (9.6, 55, 80) direction (0, 0, -1), diameter 10.376, depth 43, V-bottom angle 120, threaded "M12x1.5", thread diameter 12, thread depth 41, pitch 1.5
  DatumSurface18
  Sketch30 on face of Pad2 from Sketch5.L2, origin (0, 0, -80), H (1, 0, 0), V (0, -1, 0)
    circle A1 centre (9.6, -55) radius 6
    circle A2 centre (9.6, 53.5) radius 6
    reference projected line E1 (1.6, 80) -> (1.6, -80) from edge [face of Pocket13 from Sketch40.L2 | start face of Pocket13]
    reference projected line E2 (1.6, -75) -> (17.6, -75) from edge [face of Chamfer1 | face of Pad2 from Sketch5.L2]
    reference projected line E3 (1.6, 80) -> (17.6, 80) from edge [face of Chamfer1 | face of Pad2 from Sketch5.L3]
    radius A2 = 6
    radius A1 = 6
    distance A1 E1 = 2
    distance A1 E2 = 26
    distance A2 E1 = 2
    distance A2 E3 = 32.5
  Pocket12: profile Sketch30, direction (0, 0, 1), length 1
  DatumCurve22
  DatumCurve23
  Sketch31 on face of Pad2 from Sketch5.L1, origin (0, 80, 0), H (-1, 0, 0), V (0, 0, 1)
    projected arc E1 centre (-9.6, 10) radius 5.19 from (-9.6, 4.81) to (-9.6, 15.19) ccw from edge of DatumCurve22
    projected arc E2 centre (-9.6, 10) radius 5.19 from (-9.6, 15.19) to (-9.6, 4.81) ccw from edge of DatumCurve23
    point P5 (-9.6, 10)
    concentricity: P5 E1
  Sketch32 on face of Pad2 from Sketch5.L1, origin (9.6, 80, 10), H (1, 0, 0), V (0, 0, -1)
    point P1 (0, 0)
    reference projected point E1 (0, 0) from Sketch31.P5
    coincidence: E1 P1
  Hole10: placed by Sketch32, at (9.6, 80, 10) direction (0, -1, 0), diameter 10, depth 105, V-bottom angle 120
  Sketch33 on face of Pad2 from Sketch5.L4, origin (0, 0, 80), H (1, 0, 0), V (0, 1, 0)
    point P1 (9.5108, -34)
    reference projected line E1 (1.6, -80) -> (17.6, -80) from edge [face of Pad2 from Sketch5.L3 | face of Chamfer1]
    distance P1 E1 = 46
  Sketch34 on face of Pad2 from Sketch5.L4, origin (9.5108, -34, 80), H (1, 0, 0), V (0, 1, 0)
    point P1 (0, 0)
    reference projected point E1 (0, 0) from Sketch33.P1
    coincidence: E1 P1
  Hole11: placed by Sketch34, at (9.5108, -34, 80) direction (0, 0, -1), diameter 10, depth 102, V-bottom angle 120
  DatumCurve24
  Sketch35 on face of Pad2 from Sketch5.L2, origin (0, 0, -80), H (1, 0, 0), V (0, -1, 0)
    reference projected circle E1 centre (9.6, 53.5) radius 5 from edge of DatumCurve24
    point P1 (9.6, 53.5)
    concentricity: P1 E1
  Sketch36 on face of Pad2 from Sketch5.L2, origin (9.6, -53.5, -80), H (1, 0, 0), V (0, -1, 0)
    point P1 (0, 0)
    reference projected point E1 (0, 0) from Sketch35.P1
    coincidence: E1 P1
  Hole12: placed by Sketch36, at (9.6, -53.5, -80) direction (0, 0, 1), diameter 10, depth 58, V-bottom angle 120
  Sketch37 on face of Pad2 from Sketch5.L3, origin (0, -80, 0), H (1, 0, 0), V (0, 0, 1)
    reference projected circle E1 centre (9.6, 34.5) radius 5.188 from edge [face of Hole4 | face of Pad2 from Sketch5.L3]
    reference projected circle E2 centre (9.6, -22) radius 5.188 from edge [face of Hole5 | face of Pad2 from Sketch5.L3]
    point P1 (9.6, -22)
    point P2 (9.6, 34.5)
    concentricity: P1 E2, P2 E1
  Sketch38 on face of Pad2 from Sketch5.L1, origin (9.6, 80, 10), H (1, 0, 0), V (0, 0, -1)
    point P1 (0, 0)
    reference projected point E1 (0, 0) from Sketch31.P5
    coincidence: E1 P1
  Hole13: placed by Sketch38, at (9.6, 80, 10) direction (0, -1, 0), diameter 10.376, depth 12, V-bottom angle 120, threaded "M12x1.5", thread diameter 12, thread depth 10, pitch 1.5
  Sketch39 on face of Pad2 from Sketch5.L4, origin (9.5108, -34, 80), H (1, 0, 0), V (0, 1, 0)
    point P1 (0, 0)
    reference projected point E1 (0, 0) from Sketch33.P1
    coincidence: E1 P1
  Hole14: placed by Sketch39, at (9.5108, -34, 80) direction (0, 0, -1), diameter 10.376, depth 43, V-bottom angle 120, threaded "M12x1.5", thread diameter 12, thread depth 41, pitch 1.5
